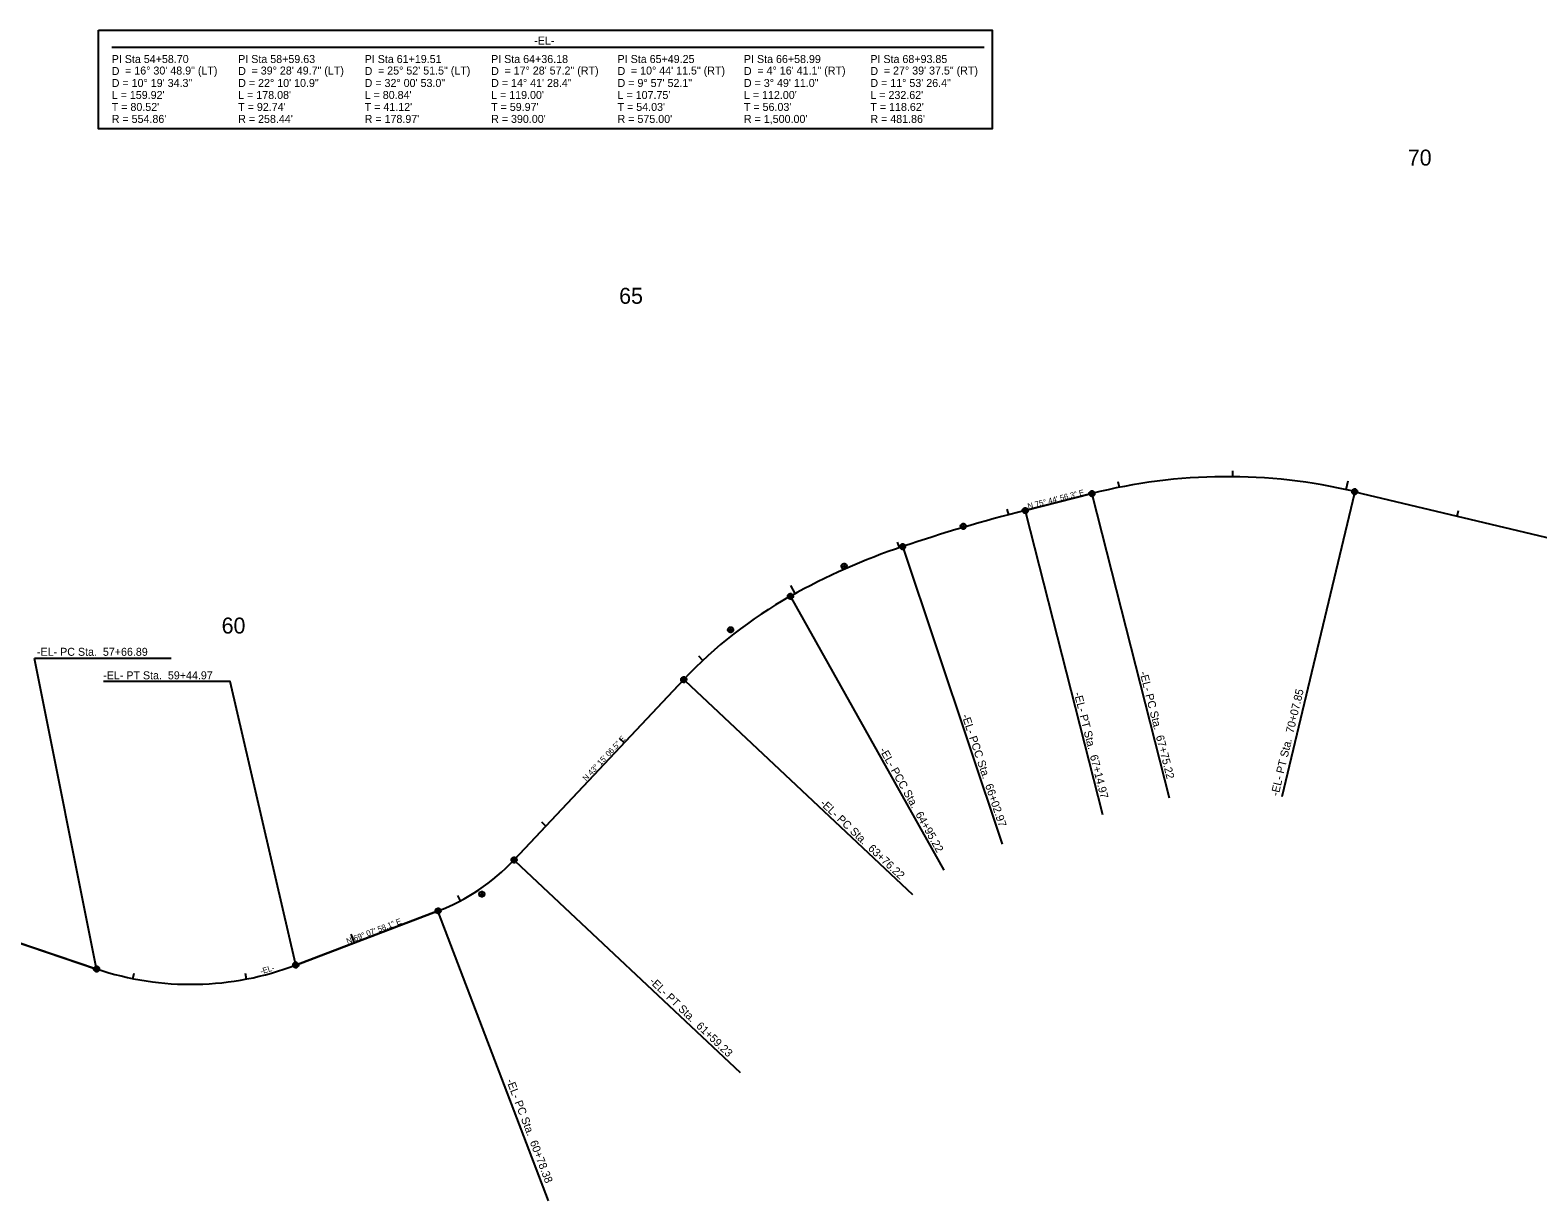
# Model space of a CAD drawing. Extents: x 928071 to 937324, y 684061 to 686812.
# Drawn here: x 932135 to 933456, y 684215 to 685241 of the extents above; entities that cross this region are included whole.
import ezdxf

# ---------------------------------------------------------------- set-up
doc = ezdxf.new("R2010")
doc.units = 0
for name, color, linetype in [('COGO Default Chain', 7, 'Continuous'), ('COGO Default Curve', 7, 'Continuous'), ('Cogo Default Point CELL', 7, 'Continuous'), ('Default', 7, 'Continuous'), ('Exist Horizontal Alignment', 7, 'Continuous'), ('Exist Horizontal Alignment Curve and Spiral Data', 7, 'Continuous'), ('Exist Horizontal Alignment Direction Label', 7, 'Continuous'), ('Exist Horizontal Alignment Station Label', 7, 'Continuous'), ('Exist Horizontal Alignment Tick Label', 7, 'Continuous'), ('Exist Horizontal Alignment Tick Large', 7, 'Continuous'), ('Exist Horizontal Alignment Tick Small', 7, 'Continuous'), ('Prop DSN Text', 7, 'Continuous')]:
    doc.layers.add(name, color=color, linetype=linetype)

msp = doc.modelspace()

# ---------------------------------------------------------------- linework, layer by layer
at = {"layer": 'COGO Default Chain'}
for p, q in [((933006.4, 684819.7), (933064.8, 684834.5)), ((933295.1, 684836.2), (933717.7, 684735.5)), ((932558.5, 684513.5), (932707.2, 684671.5)), ((931975.8, 684491), (932192.7, 684417.9)), ((932367.2, 684421.4), (932491.9, 684468.9))]:
    msp.add_line(p, q, dxfattribs=at)
for centre, radius, start, end in [((933183.4, 684367.5), 481.9, 76.5906, 104.251), ((933375.6, 683365.9), 1500, 104.251, 108.5291), ((933081.7, 684242.9), 575, 108.5291, 119.2656), ((932991.2, 684404.3), 390, 119.2656, 136.7482), ((932428.1, 684636.1), 179, 290.8672, 316.7482), ((932275.2, 684662.9), 258.4, 251.3867, 290.8672)]:
    msp.add_arc(centre, radius, start, end, dxfattribs=at)
at = {"layer": 'COGO Default Curve'}
for centre, radius, start, end in [((933183.4, 684367.5), 481.9, 76.5906, 104.251), ((933375.6, 683365.9), 1500, 104.251, 108.5291), ((933081.7, 684242.9), 575, 108.5291, 119.2656), ((932991.2, 684404.3), 390, 119.2656, 136.7482), ((932428.1, 684636.1), 179, 290.8672, 316.7482), ((932275.2, 684662.9), 258.4, 251.3867, 290.8672)]:
    msp.add_arc(centre, radius, start, end, dxfattribs=at)
at = {"layer": 'Cogo Default Point CELL'}
for points in [[(933295.1, 684839.2), (933295.1, 684836.2)], [(933061.8, 684834.5), (933064.8, 684834.5)], [(933064.8, 684837.5), (933064.8, 684834.5)], [(933064.8, 684834.5), (933067.8, 684834.5)], [(933064.8, 684834.5), (933064.8, 684831.5)], [(933292.1, 684836.2), (933295.1, 684836.2)], [(933295.1, 684836.2), (933298.1, 684836.2)], [(933295.1, 684836.2), (933295.1, 684833.2)], [(933003.4, 684819.7), (933006.4, 684819.7)], [(933006.4, 684822.7), (933006.4, 684819.7)], [(933006.4, 684819.7), (933009.4, 684819.7)], [(933006.4, 684819.7), (933006.4, 684816.7)], [(932949.1, 684805.9), (932952.1, 684805.9)], [(932952.1, 684808.9), (932952.1, 684805.9)], [(932952.1, 684805.9), (932955.1, 684805.9)], [(932952.1, 684805.9), (932952.1, 684802.9)], [(932895.9, 684788.1), (932898.9, 684788.1)], [(932895.9, 684788.1), (932898.9, 684788.1)], [(932898.9, 684791.1), (932898.9, 684788.1)], [(932898.9, 684791.1), (932898.9, 684788.1)], [(932898.9, 684788.1), (932901.9, 684788.1)], [(932898.9, 684788.1), (932898.9, 684785.1)], [(932898.9, 684788.1), (932901.9, 684788.1)], [(932898.9, 684788.1), (932898.9, 684785.1)], [(932847.7, 684773.9), (932847.7, 684770.9)], [(932844.7, 684770.9), (932847.7, 684770.9)], [(932847.7, 684770.9), (932850.7, 684770.9)], [(932847.7, 684770.9), (932847.7, 684767.9)], [(932800.6, 684747.5), (932800.6, 684744.5)], [(932800.6, 684747.5), (932800.6, 684744.5)], [(932797.6, 684744.5), (932800.6, 684744.5)], [(932797.6, 684744.5), (932800.6, 684744.5)], [(932800.6, 684744.5), (932803.6, 684744.5)], [(932800.6, 684744.5), (932800.6, 684741.5)], [(932800.6, 684744.5), (932803.6, 684744.5)], [(932800.6, 684744.5), (932800.6, 684741.5)], [(932745.2, 684715.2), (932748.2, 684715.2)], [(932748.2, 684718.2), (932748.2, 684715.2)], [(932748.2, 684715.2), (932751.2, 684715.2)], [(932748.2, 684715.2), (932748.2, 684712.2)], [(932704.2, 684671.5), (932707.2, 684671.5)], [(932707.2, 684674.5), (932707.2, 684671.5)], [(932707.2, 684671.5), (932710.2, 684671.5)], [(932707.2, 684671.5), (932707.2, 684668.5)], [(932555.5, 684513.5), (932558.5, 684513.5)], [(932558.5, 684516.5), (932558.5, 684513.5)], [(932558.5, 684513.5), (932561.5, 684513.5)], [(932558.5, 684513.5), (932558.5, 684510.5)], [(932527.3, 684483.5), (932530.3, 684483.5)], [(932530.3, 684486.5), (932530.3, 684483.5)], [(932530.3, 684483.5), (932533.3, 684483.5)], [(932530.3, 684483.5), (932530.3, 684480.5)], [(932488.9, 684468.9), (932491.9, 684468.9)], [(932491.9, 684471.9), (932491.9, 684468.9)], [(932491.9, 684468.9), (932494.9, 684468.9)], [(932491.9, 684468.9), (932491.9, 684465.9)], [(932189.7, 684417.9), (932192.7, 684417.9)], [(932192.7, 684420.9), (932192.7, 684417.9)], [(932192.7, 684417.9), (932195.7, 684417.9)], [(932192.7, 684417.9), (932192.7, 684414.9)], [(932364.2, 684421.4), (932367.2, 684421.4)], [(932367.2, 684424.4), (932367.2, 684421.4)], [(932367.2, 684421.4), (932370.2, 684421.4)], [(932367.2, 684421.4), (932367.2, 684418.4)]]:
    msp.add_lwpolyline(points, dxfattribs=at)
for centre in [(933295.1, 684836.2), (933064.8, 684834.5), (933006.4, 684819.7), (932952.1, 684805.9), (932898.9, 684788.1), (932898.9, 684788.1), (932847.7, 684770.9), (932800.6, 684744.5), (932800.6, 684744.5), (932748.2, 684715.2), (932707.2, 684671.5), (932558.5, 684513.5), (932530.3, 684483.5), (932491.9, 684468.9), (932192.7, 684417.9), (932367.2, 684421.4)]:
    msp.add_circle(centre, 2.34, dxfattribs=at)
at = {"layer": 'Default'}
for p, q in [((933064.8, 684834.5), (933006.4, 684819.7)), ((933295.1, 684836.2), (933717.7, 684735.5)), ((932707.2, 684671.5), (932558.5, 684513.5)), ((932192.7, 684417.9), (931975.8, 684491)), ((932491.9, 684468.9), (932367.2, 684421.4))]:
    msp.add_line(p, q, dxfattribs=at)
msp.add_lwpolyline([(932194.4, 685240.7), (932977.3, 685240.7), (932977.3, 685154.1), (932194.4, 685154.1)], close=True, dxfattribs=at)
for centre, radius, start, end in [((933183.4, 684367.5), 481.9, 76.5906, 104.251), ((933375.6, 683365.9), 1500, 104.251, 108.5291), ((933081.7, 684242.9), 575, 108.5291, 119.2656), ((932991.2, 684404.3), 390, 119.2656, 136.7482), ((932428.1, 684636.1), 179, 290.8672, 316.7482), ((932275.2, 684662.9), 258.4, 251.3867, 290.8672)]:
    msp.add_arc(centre, radius, start, end, dxfattribs=at)
at = {"layer": 'Exist Horizontal Alignment'}
for p, q in [((933006.4, 684819.7), (933064.8, 684834.5)), ((933295.1, 684836.2), (933717.7, 684735.5)), ((932558.5, 684513.5), (932707.2, 684671.5)), ((931975.8, 684491), (932192.7, 684417.9)), ((932367.2, 684421.4), (932491.9, 684468.9))]:
    msp.add_line(p, q, dxfattribs=at)
for centre, radius, start, end in [((933183.4, 684367.5), 481.9, 76.5906, 104.251), ((933375.6, 683365.9), 1500, 104.251, 108.5291), ((933081.7, 684242.9), 575, 108.5291, 119.2656), ((932991.2, 684404.3), 390, 119.2656, 136.7482), ((932428.1, 684636.1), 179, 290.8672, 316.7482), ((932275.2, 684662.9), 258.4, 251.3867, 290.8672)]:
    msp.add_arc(centre, radius, start, end, dxfattribs=at)
at = {"layer": 'Exist Horizontal Alignment Curve and Spiral Data'}
for p, q in [((932206.2, 685225.8), (932970.4, 685225.8)), ((932870.7, 685211.9), (932870.7, 685211.9))]:
    msp.add_line(p, q, dxfattribs=at)
at = {"layer": 'Exist Horizontal Alignment Station Label'}
for p, q in [((933065.1, 684833.1), (933132.5, 684568)), ((933294.8, 684834.8), (933231.3, 684568.7)), ((933006.7, 684818.3), (933074, 684553.2)), ((932899.4, 684786.7), (932986.3, 684527.4)), ((932801.3, 684743.2), (932935, 684504.6)), ((932192.3, 684419.4), (932138.2, 684690.1)), ((932258.1, 684690.1), (932138.2, 684690.1)), ((932708.3, 684670.5), (932907.5, 684483.1)), ((932559.6, 684512.5), (932756.6, 684327.1)), ((932588.8, 684214.7), (932492.4, 684467.5))]:
    msp.add_line(p, q, dxfattribs=at)
msp.add_lwpolyline([(932366.9, 684422.8), (932309.8, 684669.8), (932198.9, 684669.8)], dxfattribs=at)
for centre in [(933295.1, 684836.2), (933064.8, 684834.5), (933006.4, 684819.7), (932898.9, 684788.1), (932800.6, 684744.5), (932707.2, 684671.5), (932558.5, 684513.5), (932491.9, 684468.9), (932192.7, 684417.9), (932367.2, 684421.4)]:
    msp.add_circle(centre, 1.5, dxfattribs=at)
at = {"layer": 'Exist Horizontal Alignment Tick Large'}
for p, q in [((933287.5, 684838), (933289.2, 684845.8)), ((932804.7, 684746.9), (932800.9, 684753.9)), ((932418.6, 684441), (932415.8, 684448.5))]:
    msp.add_line(p, q, dxfattribs=at)
at = {"layer": 'Exist Horizontal Alignment Tick Small'}
for p, q in [((933188.3, 684849.4), (933188.4, 684854.4)), ((933088.9, 684840), (933087.9, 684844.9)), ((932991.9, 684816), (932990.6, 684820.8)), ((933384.8, 684814.9), (933385.9, 684819.7)), ((932896.1, 684787.2), (932894.5, 684791.9)), ((932724, 684688.4), (932720.5, 684692)), ((932654.9, 684616), (932651.3, 684619.5)), ((932586.4, 684543.2), (932582.8, 684546.6)), ((932511.6, 684477.8), (932509.2, 684482.2)), ((932224.6, 684409.4), (932225.6, 684414.3)), ((932324, 684409.1), (932323.1, 684414))]:
    msp.add_line(p, q, dxfattribs=at)

# ---------------------------------------------------------------- texts
at = {"layer": 'Exist Horizontal Alignment Curve and Spiral Data'}
for s, p in [('-EL-', (932576.2, 685228.1)), ('PI Sta 54+58.70', (932206, 685211.9)), ('D', (932206, 685201.4)), ('= 16%%d 30\' 48.9" (LT)', (932217.7, 685201.8)), ('PI Sta 58+59.63', (932316.8, 685211.9)), ('D', (932316.8, 685201.4)), ('= 39%%d 28\' 49.7" (LT)', (932328.5, 685201.8)), ('PI Sta 61+19.51', (932427.6, 685211.9)), ('D', (932427.6, 685201.4)), ('= 25%%d 52\' 51.5" (LT)', (932439.3, 685201.8)), ('PI Sta 64+36.18', (932538.4, 685211.9)), ('D', (932538.4, 685201.4)), ('= 17%%d 28\' 57.2" (RT)', (932550.1, 685201.8)), ('PI Sta 65+49.25', (932649.2, 685211.9)), ('D', (932649.2, 685201.4)), ('= 10%%d 44\' 11.5" (RT)', (932660.9, 685201.8)), ('PI Sta 66+58.99', (932759.9, 685211.9)), ('D', (932759.9, 685201.4)), ('= 4%%d 16\' 41.1" (RT)', (932771.7, 685201.8)), ('PI Sta 68+93.85', (932870.7, 685211.9)), ('D', (932870.7, 685201.4)), ('= 27%%d 39\' 37.5" (RT)', (932882.5, 685201.8)), ('D = 10%%d 19\' 34.3"', (932206, 685190.9)), ('D = 22%%d 10\' 10.9"', (932316.8, 685190.9)), ('D = 32%%d 00\' 53.0"', (932427.6, 685190.9)), ('D = 14%%d 41\' 28.4"', (932538.4, 685190.9)), ('D = 9%%d 57\' 52.1"', (932649.2, 685190.9)), ('D = 3%%d 49\' 11.0"', (932759.9, 685190.9)), ('D = 11%%d 53\' 26.4"', (932870.7, 685190.9)), ("L = 159.92'", (932206, 685180.4)), ("L = 178.08'", (932316.8, 685180.4)), ("L = 80.84'", (932427.6, 685180.4)), ("L = 119.00'", (932538.4, 685180.4)), ("L = 107.75'", (932649.2, 685180.4)), ("L = 112.00'", (932759.9, 685180.4)), ("L = 232.62'", (932870.7, 685180.4)), ("T = 80.52'", (932206, 685169.9)), ("T = 92.74'", (932316.8, 685169.9)), ("T = 41.12'", (932427.6, 685169.9)), ("T = 59.97'", (932538.4, 685169.9)), ("T = 54.03'", (932649.2, 685169.9)), ("T = 56.03'", (932759.9, 685169.9)), ("T = 118.62'", (932870.7, 685169.9)), ("R = 554.86'", (932206, 685159.4)), ("R = 258.44'", (932316.8, 685159.4)), ("R = 178.97'", (932427.6, 685159.4)), ("R = 390.00'", (932538.4, 685159.4)), ("R = 575.00'", (932649.2, 685159.4)), ("R = 1,500.00'", (932759.9, 685159.4)), ("R = 481.86'", (932870.7, 685159.4))]:
    msp.add_text(s, height=7, dxfattribs=at).set_placement(p)
at = {"layer": 'Exist Horizontal Alignment Direction Label'}
for s, rotation, p in [('N 75%%d 44\' 56.3" E', 14.251, (933009.1, 684820.9)), ('N 43%%d 15\' 06.5" E', 46.7482, (932621.6, 684582.3)), ('N 69%%d 07\' 58.1" E', 20.8672, (932412.7, 684439.7))]:
    msp.add_text(s, height=5, rotation=rotation, dxfattribs=at).set_placement(p)
at = {"layer": 'Exist Horizontal Alignment Station Label'}
for s, rotation, p in [('-EL- PC Sta.  57+66.89', 360, (932140.5, 684692.4)), ('-EL- PC Sta.  67+75.22', 284.251, (933106.6, 684677.9)), ('-EL- PT Sta.  67+14.97', 284.251, (933049, 684659.7)), ('-EL- PT Sta.  70+07.85', 76.5906, (933228.2, 684569)), ('-EL- PCC Sta.  66+02.97', 288.5291, (932950.6, 684640.1)), ('-EL- PCC Sta.  64+95.22', 299.2656, (932878.4, 684609.8)), ('-EL- PC Sta.  63+76.22', 316.7482, (932826.1, 684562.4)), ('-EL- PT Sta.  61+59.23', 316.3792, (932676.5, 684406.4)), ('-EL- PC Sta.  60+78.38', 290.8672, (932551.6, 684320.2))]:
    msp.add_text(s, height=7, rotation=rotation, dxfattribs=at).set_placement(p)
msp.add_text('-EL- PT Sta.  59+44.97', height=7, dxfattribs=at).set_placement((932198.5, 684671.8))
at = {"layer": 'Exist Horizontal Alignment Tick Label'}
for s, p in [('70', (933341.6, 685122)), ('65', (932650.6, 685000.9)), ('60', (932302.3, 684711.9))]:
    msp.add_text(s, height=14, dxfattribs=at).set_placement(p)
at = {"layer": 'Prop DSN Text'}
msp.add_text('-EL-', height=5, rotation=16.6399, dxfattribs=at).set_placement((932336.9, 684413.3))

doc.saveas('drawing.dxf')
